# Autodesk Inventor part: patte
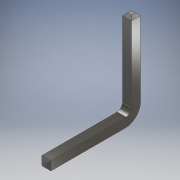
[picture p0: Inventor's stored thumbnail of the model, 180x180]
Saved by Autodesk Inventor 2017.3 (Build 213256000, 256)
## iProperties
Part Number: patte
Material: Générique
Document SubType Name: Modeling
Designer: ficho
Density: 1 g/cm^3
Appearance: Acier - Poli
Author: ficho
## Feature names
1. Balayage1
2. Chanfrein1 [Chamfer]
## Parameters: d0 = 0.7 mm, d1 = 0.7 mm, d2 = 6 mm, d3 = 1 mm, d4 = 6 mm, d5 = 0, d6 = 0, d7 = 0.2 mm, d8 = 2 mm, d9 = 45 deg
